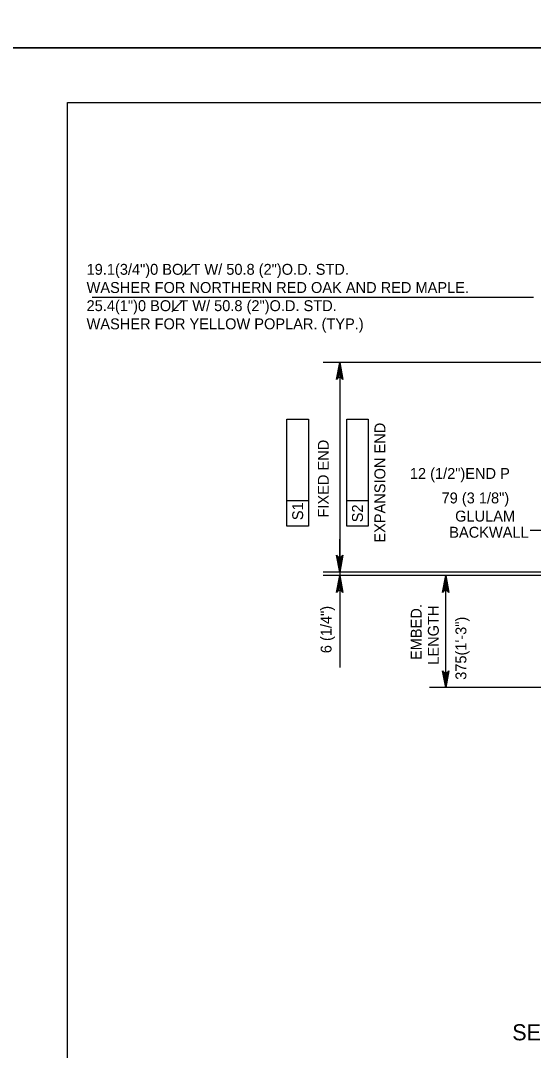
# Model space of a CAD drawing. Extents: x 638175 to 640495, y 294277 to 298435.
# Drawn here: x 639303.6 to 639444.7, y 297565.7 to 297849 of the extents above; entities that cross this region are included whole.
import ezdxf

# ---------------------------------------------------------------- set-up
doc = ezdxf.new("R2010")
doc.units = 0
for name, color, linetype in [('2', 7, 'Continuous'), ('3', 7, 'Continuous'), ('PLT-BNDY', 7, 'Continuous')]:
    doc.layers.add(name, color=color, linetype=linetype)

msp = doc.modelspace()

# ---------------------------------------------------------------- linework, layer by layer
at = {"layer": '2'}
for p, q in [((639316.46, 297262.46), (639316.46, 297826.46)), ((639316.46, 297826.46), (640102.46, 297826.46))]:
    msp.add_line(p, q, dxfattribs=at)
at = {"layer": '3'}
for p, q in [((639351.01, 297781.84), (639348.09, 297778.92)), ((639444.66, 297772.77), (639323.29, 297772.77)), ((639348.06, 297771.78), (639345.14, 297768.86)), ((639458.95, 297754.9), (639386.86, 297754.9)), ((639413.66, 297754.9), (639386.86, 297754.9)), ((639391.36, 297754.9), (639391.36, 297700.79)), ((639391.36, 297751.9), (639391.36, 297700.28)), ((639376.84, 297739.33), (639382.74, 297739.33)), ((639376.84, 297709.94), (639376.84, 297739.33)), ((639382.74, 297739.33), (639382.74, 297709.94)), ((639393.29, 297709.94), (639393.29, 297739.33)), ((639393.29, 297739.33), (639399.19, 297739.33)), ((639399.19, 297739.33), (639399.19, 297709.94)), ((639382.74, 297716.83), (639376.84, 297716.83)), ((639399.19, 297716.83), (639393.29, 297716.83)), ((639382.74, 297709.94), (639376.84, 297709.94)), ((639399.19, 297709.94), (639393.29, 297709.94)), ((639446.73, 297708.74), (639443.73, 297708.74)), ((639391.36, 297701.78), (639391.36, 297706.28)), ((639391.36, 297700.28), (639391.36, 297703.28)), ((639458.95, 297697.28), (639386.86, 297697.28)), ((639413.66, 297697.28), (639386.86, 297697.28)), ((639467.56, 297696.29), (639386.86, 297696.29)), ((639389.79, 297696.29), (639386.86, 297696.29)), ((639391.36, 297697.28), (639391.36, 297696.29)), ((639458.95, 297696.29), (639416.03, 297696.29)), ((639418.97, 297696.29), (639416.03, 297696.29)), ((639420.53, 297665.48), (639420.53, 297696.29)), ((639391.36, 297693.29), (639391.36, 297690.29)), ((639420.53, 297668.48), (639420.53, 297693.29)), ((639391.36, 297691.79), (639391.36, 297670.99)), ((639488.4, 297665.48), (639416.03, 297665.48)), ((639418.97, 297665.48), (639416.03, 297665.48))]:
    msp.add_line(p, q, dxfattribs=at)
for points in [[(639391.36, 297754.9), (639392.23, 297750.24), (639391.98, 297750.59), (639391.67, 297750.78), (639391.36, 297750.83), (639391.04, 297750.78), (639390.73, 297750.59), (639390.48, 297750.24), (639391.36, 297754.9), (639390.73, 297750.59), (639391.04, 297750.78), (639391.36, 297754.9), (639391.36, 297750.83), (639391.67, 297750.78), (639391.36, 297754.9), (639391.98, 297750.59)], [(639391.36, 297697.28), (639390.48, 297701.94), (639390.73, 297701.58), (639391.04, 297701.4), (639391.36, 297701.35), (639391.67, 297701.4), (639391.98, 297701.58), (639392.23, 297701.94), (639391.36, 297697.28), (639391.98, 297701.58), (639391.67, 297701.4), (639391.36, 297697.28), (639391.36, 297701.35), (639391.04, 297701.4), (639391.36, 297697.28), (639390.73, 297701.58)], [(639391.36, 297696.29), (639392.23, 297691.63), (639391.98, 297691.99), (639391.67, 297692.18), (639391.36, 297692.23), (639391.04, 297692.18), (639390.73, 297691.99), (639390.48, 297691.63), (639391.36, 297696.29), (639390.73, 297691.99), (639391.04, 297692.18), (639391.36, 297696.29), (639391.36, 297692.23), (639391.67, 297692.18), (639391.36, 297696.29), (639391.98, 297691.99)], [(639420.53, 297696.29), (639421.41, 297691.63), (639421.16, 297691.99), (639420.85, 297692.18), (639420.53, 297692.23), (639420.22, 297692.18), (639419.91, 297691.99), (639419.66, 297691.63), (639420.53, 297696.29), (639419.91, 297691.99), (639420.22, 297692.18), (639420.53, 297696.29), (639420.53, 297692.23), (639420.85, 297692.18), (639420.53, 297696.29), (639421.16, 297691.99)], [(639420.53, 297665.48), (639419.66, 297670.14), (639419.91, 297669.78), (639420.22, 297669.6), (639420.53, 297669.54), (639420.85, 297669.6), (639421.16, 297669.78), (639421.41, 297670.14), (639420.53, 297665.48), (639421.16, 297669.78), (639420.85, 297669.6), (639420.53, 297665.48), (639420.53, 297669.54), (639420.22, 297669.6), (639420.53, 297665.48), (639419.91, 297669.78)]]:
    msp.add_lwpolyline(points, dxfattribs=at)
for points in [[(639390.86, 297751.9), (639391.86, 297751.9), (639391.36, 297754.9)], [(639390.86, 297700.28), (639391.86, 297700.28), (639391.36, 297697.28)], [(639390.86, 297693.29), (639391.86, 297693.29), (639391.36, 297696.29)], [(639420.03, 297693.29), (639421.03, 297693.29), (639420.53, 297696.29)], [(639420.03, 297668.48), (639421.03, 297668.48), (639420.53, 297665.48)]]:
    msp.add_lwpolyline(points, close=True, dxfattribs=at)
at = {"layer": 'PLT-BNDY'}
for points in [[(639276.46, 298435.46), (640117.46, 298435.46), (640117.46, 297841.46), (639276.46, 297841.46)], [(639276.46, 297841.46), (640117.46, 297841.46), (640117.46, 297247.46), (639276.46, 297247.46)]]:
    msp.add_lwpolyline(points, close=True, dxfattribs=at)

# ---------------------------------------------------------------- texts
at = {"layer": '3'}
for s, height, p in [('19.1(3/4")0 BOLT W/ 50.8 (2")O.D. STD. ', 3, (639321.73, 297779.04)), ('WASHER FOR NORTHERN RED OAK AND RED MAPLE.', 3, (639321.73, 297774.04)), ('25.4(1")0 BOLT W/ 50.8 (2")O.D. STD.', 3, (639321.73, 297769.04)), ('WASHER FOR YELLOW POPLAR. (TYP.) ', 3, (639321.73, 297764.04)), ('12 (1/2")END P', 3, (639410.67, 297722.89)), ('79 (3 1/8")', 3, (639419.4, 297716.16)), ('GLULAM', 3, (639423.13, 297711.16)), ('BACKWALL', 3, (639421.51, 297706.72)), ('SECTION VIEW AT BEARING', 4.4292, (639438.84, 297568.47))]:
    msp.add_text(s, height=height, dxfattribs=at).set_placement(p)
for s, p in [('EXPANSION END', (639403.93, 297705.36)), ('FIXED END', (639388.36, 297712.27)), ('S1', (639381.31, 297711.55)), ('S2', (639397.76, 297710.96)), ('6 (1/4")', (639389.13, 297674.95)), ('EMBED.', (639413.92, 297673.08)), ('LENGTH', (639418.63, 297671.78)), ('375(1\'-3")', (639426.22, 297667.63))]:
    msp.add_text(s, height=3, rotation=90, dxfattribs=at).set_placement(p)

doc.saveas('drawing.dxf')
